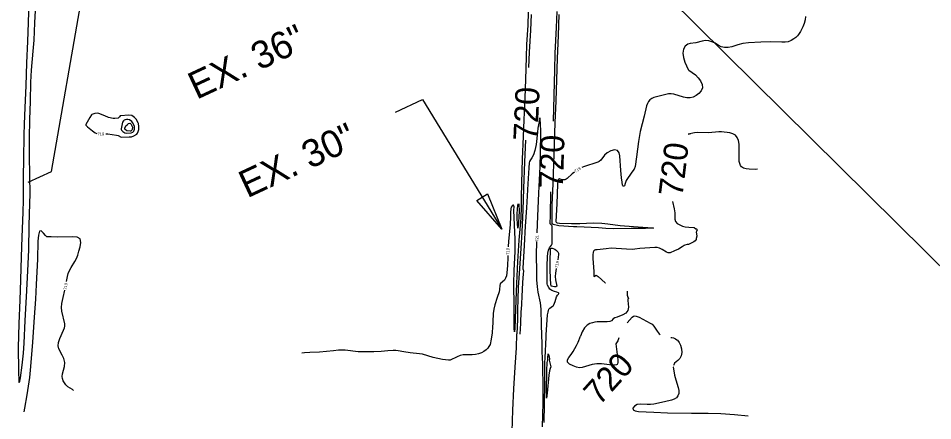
# Model space of a CAD drawing. Extents: x -310467766 to 17062430, y -322263100 to 8322522.
# Drawn here: x 1394958 to 1396211, y 571595 to 572146 of the extents above; entities that cross this region are included whole.
import ezdxf

# ---------------------------------------------------------------- set-up
doc = ezdxf.new("R2010")
doc.units = 0
for name, color, linetype in [('DT_X_Contour_Minor', 7, 'Continuous'), ('Level 19', 7, 'Continuous'), ('Level 40', 7, 'Continuous')]:
    doc.layers.add(name, color=color, linetype=linetype)

msp = doc.modelspace()

# ---------------------------------------------------------------- linework, layer by layer
at = {"layer": 'DT_X_Contour_Minor'}
for points in [[(1394972.9, 572168.3), (1394972, 572140.1), (1394970.9, 572114.2), (1394969.7, 572084.7), (1394968.7, 572053.5), (1394967.4, 572023.7), (1394966.5, 572000.8), (1394965.8, 571986.2), (1394965.3, 571952.4), (1394965.1, 571929.4), (1394965.2, 571897.1), (1394964.7, 571880.6), (1394963.1, 571846.3), (1394962.3, 571819.1), (1394961.5, 571788), (1394960.3, 571759.8), (1394959.2, 571728.2), (1394958.4, 571694.7), (1394958.7, 571664), (1394959.2, 571647.6), (1394959.4, 571647.3), (1394959.8, 571647.5), (1394960.5, 571649.1), (1394961.4, 571653.5), (1394963.8, 571670.9), (1394965.6, 571687.2), (1394966.6, 571700.9), (1394968, 571732), (1394969.8, 571764.6), (1394971.6, 571800.1), (1394972.6, 571828.8), (1394973.4, 571862.3), (1394974.4, 571892.1), (1394974.5, 571905.7), (1394974.2, 571930.3), (1394973.7, 571958.4), (1394973.9, 571981.6), (1394974.3, 572007.5), (1394975.2, 572031.9), (1394975.4, 572058.4), (1394976.3, 572074.9), (1394978.8, 572101.1), (1394980, 572115.8), (1394981.1, 572139.7), (1394982.3, 572165)], [(1395656.8, 572154.4), (1395656, 572136.7), (1395654.5, 572109.9), (1395653.7, 572092.6), (1395652.9, 572062), (1395651.9, 572037.2), (1395650.6, 572007.1), (1395649.6, 571984.1), (1395648.3, 571952.9), (1395647.4, 571920.5), (1395647, 571900), (1395646.9, 571888.1), (1395646.4, 571872.2), (1395645.3, 571857.1), (1395643.9, 571842.1), (1395642.2, 571812.7), (1395640.8, 571782.8), (1395639.4, 571747.7), (1395638.2, 571721.2), (1395637.7, 571716.7), (1395637.5, 571721.2), (1395637.5, 571751.8), (1395637.2, 571782.2), (1395637.6, 571800.8), (1395638.6, 571826.5), (1395638.7, 571843.6), (1395638, 571862.6), (1395637.1, 571883), (1395637.4, 571887.7), (1395637.2, 571889.3), (1395636.7, 571890.1), (1395635.7, 571890), (1395634.6, 571889), (1395633.5, 571887.3), (1395632.9, 571885.1), (1395632.5, 571880.2), (1395632.6, 571874.4), (1395632, 571863), (1395629.8, 571840.7), (1395629.1, 571833.2)], [(1395660.8, 572151.1), (1395659.7, 572129.5), (1395658.1, 572099.3), (1395657.1, 572078.7)], [(1395719.9, 571935.4), (1395716.8, 571932.8), (1395710, 571926.4), (1395708.6, 571925.5), (1395706.9, 571924.9), (1395704.9, 571924.6), (1395702.9, 571924.8), (1395699.4, 571926), (1395698.2, 571925.4), (1395697.4, 571923), (1395697, 571918.8), (1395695.8, 571891.9), (1395694.7, 571867.5), (1395695, 571866.8), (1395695.5, 571866.3), (1395696.3, 571866), (1395699.7, 571865.6), (1395715.8, 571865), (1395727.5, 571864.9), (1395745.6, 571865.7), (1395757.3, 571865.2), (1395765.9, 571864.4), (1395782.6, 571862.1), (1395800.7, 571860.7), (1395826.7, 571859), (1395828.3, 571858.7), (1395827.2, 571858.4), (1395817.1, 571858), (1395797.9, 571858.1), (1395773.7, 571857.8), (1395763.1, 571858.3), (1395752.8, 571858.8), (1395723.1, 571860.2), (1395718.7, 571860.6), (1395698.6, 571861.7), (1395690.9, 571863.5), (1395689.6, 571864.6), (1395689.4, 571865.2), (1395689.4, 571873.7), (1395689.7, 571890.7), (1395690.7, 571919.1), (1395691.7, 571946.5), (1395692.5, 571973.7), (1395693.6, 572003.2), (1395694.8, 572032.4), (1395695.7, 572062.1), (1395696.6, 572091), (1395698, 572122.4), (1395699.3, 572151.2)], [(1395691.4, 572004.9), (1395692.4, 572040.4), (1395693, 572075.5), (1395693.8, 572098.1), (1395695.5, 572133.5), (1395696.3, 572155.1)], [(1396036.6, 572148.3), (1396036, 572143.8), (1396034.6, 572138.9), (1396032.8, 572134.3), (1396029.5, 572127.8), (1396026.9, 572123.6), (1396025.4, 572121.8), (1396023.4, 572119.8), (1396020.4, 572117.6), (1396016.6, 572115.5), (1396012.5, 572113.9), (1396008.4, 572113.2), (1396004.2, 572113), (1395988.5, 572113.7), (1395975.3, 572113.4), (1395958.5, 572112.4), (1395950.6, 572111.4), (1395943.7, 572109.7), (1395935.4, 572107), (1395930.5, 572105.9), (1395925.6, 572105.7), (1395921, 572107), (1395916.7, 572109.3), (1395912.5, 572111.7), (1395908.3, 572113.8), (1395904.1, 572115.1), (1395899.7, 572115.4), (1395895.1, 572114.6), (1395886.2, 572112.1), (1395878.6, 572111.3), (1395875.1, 572110.3), (1395871.8, 572107.7), (1395869.3, 572103.7), (1395868.3, 572098.3), (1395869.2, 572092), (1395871.3, 572085.8), (1395875.7, 572075.9), (1395876.8, 572074.8), (1395885.6, 572068.4), (1395889.5, 572064.6), (1395892.8, 572060.1), (1395894.9, 572055.4), (1395895.2, 572050.7), (1395893.5, 572046.5), (1395890.3, 572042.9), (1395886.5, 572040), (1395882.6, 572037.9), (1395878.5, 572036.9), (1395874.1, 572036.8), (1395869.2, 572037.8), (1395855.9, 572042), (1395852.5, 572042.5), (1395849, 572042.4), (1395845, 572041.7), (1395832.5, 572038.4), (1395828.9, 572037.3), (1395825.8, 572036), (1395823.3, 572034.3), (1395821.3, 572032.1), (1395819.9, 572029.3), (1395818.8, 572026), (1395815.6, 572011.9), (1395810, 571991.1), (1395807.7, 571977.3), (1395804.8, 571956), (1395803.2, 571943), (1395801.6, 571939.4), (1395798.8, 571935), (1395790.8, 571923.8), (1395789.7, 571921.1), (1395789, 571918.2), (1395788.9, 571917.3), (1395788.4, 571916.6), (1395787.7, 571916.2), (1395786.9, 571916.2), (1395786.3, 571916.6), (1395786, 571917.3), (1395785.5, 571921.4), (1395784.5, 571927.5), (1395783.6, 571937.6), (1395782.3, 571957.4), (1395781.2, 571961.7), (1395778.8, 571964.7), (1395774.8, 571965.6), (1395769.8, 571964.5), (1395765, 571961.9), (1395761.3, 571958.4), (1395756, 571951.6), (1395753.9, 571949.7), (1395752, 571948.7), (1395732.6, 571942.5), (1395730.3, 571941.5)], [(1395078.1, 571987.5), (1395080.9, 571987.6), (1395093, 571985.8), (1395095.3, 571985.2), (1395099.4, 571983), (1395110.3, 571983.4), (1395113.3, 571983.7), (1395116.5, 571984.9), (1395120.5, 571987.1), (1395121.7, 571988.7), (1395122.6, 571990.8), (1395123.4, 571993.6), (1395123.4, 571997.9), (1395122.8, 572001.7), (1395122.4, 572002.8), (1395119.6, 572007.7), (1395117.6, 572009.9), (1395115.9, 572011.4), (1395113.7, 572012.6), (1395109.6, 572013.1), (1395098.4, 572012.5), (1395097.7, 572012.2), (1395096.8, 572011), (1395095.7, 572009.4), (1395095.2, 572009.1), (1395090.8, 572008.7), (1395088.1, 572008.8), (1395082, 572010.2), (1395077.1, 572012.2), (1395068.8, 572015.7), (1395066.7, 572015.9), (1395063.2, 572015.6), (1395059.3, 572014.1), (1395058.7, 572013.7), (1395056.3, 572009.9), (1395052.5, 572003.6), (1395050.8, 572000.5), (1395051, 571999.8), (1395053.2, 571997.5), (1395059.9, 571991.8), (1395063.6, 571989.3), (1395066.1, 571988.2)], [(1395106.7, 572007.2), (1395104.7, 572006.9), (1395103.4, 572006.4), (1395102.4, 572005.5), (1395101.3, 572003.5), (1395099.1, 571994.7), (1395099.1, 571993.8), (1395099.6, 571992.8), (1395101.7, 571990.7), (1395104.3, 571988.9), (1395106.7, 571988.7), (1395113.1, 571989), (1395115.3, 571990.1), (1395116.5, 571991.2), (1395117.2, 571992.6), (1395117.5, 571994.2), (1395117.5, 571997.8), (1395116.7, 572000.1), (1395115, 572003.2), (1395113.7, 572004.5), (1395110.7, 572006.8), (1395108.3, 572007.2), (1395106.7, 572007.2)], [(1395112.4, 572001.5), (1395114.6, 571996.7), (1395114.5, 571993.5), (1395114, 571992.6), (1395112.5, 571991.5), (1395111.4, 571991.2), (1395106.9, 571991.9), (1395104.8, 571993.5), (1395104.2, 571994.3), (1395104.5, 571995.5), (1395105.8, 571998.7), (1395107.5, 572000.2), (1395109.5, 572001.7), (1395111.2, 572002.3), (1395112, 572002), (1395112.4, 572001.5)], [(1395668.9, 571852.1), (1395669.8, 571875.2), (1395671.1, 571906.4), (1395673.1, 571943.1), (1395673.6, 571961.3), (1395673.8, 571989.9), (1395673.4, 572002.9), (1395672.8, 572009.4), (1395672.4, 572008.5), (1395669.9, 571995.4), (1395669.2, 571990.2), (1395667.4, 571973.2), (1395665.9, 571964.9), (1395663.8, 571958.9), (1395661.6, 571954.9), (1395659.8, 571952.1), (1395658.6, 571949.9), (1395658.1, 571947.9), (1395657.6, 571941.3), (1395656.2, 571919.1), (1395654.4, 571886.4), (1395652.6, 571861.2), (1395651.2, 571834.9), (1395649.3, 571803.9), (1395649.5, 571802.4), (1395649.8, 571801.8), (1395650.1, 571799.6), (1395649.9, 571795.9), (1395648.9, 571784), (1395647.8, 571764.8), (1395647.6, 571755), (1395646.9, 571747.3), (1395646.6, 571744.8), (1395646.3, 571728), (1395645.4, 571713.6)], [(1395970.5, 571939.2), (1395967.7, 571939.1), (1395959.4, 571939.5), (1395955.2, 571940), (1395951.6, 571940.9), (1395949, 571942.5), (1395947.3, 571944.5), (1395946.3, 571947), (1395945.8, 571949.7), (1395945.8, 571957.1), (1395945.8, 571968), (1395945.4, 571973.6), (1395944.5, 571978.7), (1395942.9, 571982.9), (1395940.4, 571986), (1395936.9, 571987.9), (1395932.8, 571988.9), (1395921.4, 571990.3), (1395917.6, 571990.3), (1395903.7, 571989.2), (1395889.2, 571989.6), (1395884.3, 571989.1), (1395875.6, 571987.3), (1395879.4, 571988.1)], [(1395652.8, 571979.2), (1395651.7, 571949.2), (1395650.3, 571912.8), (1395649.3, 571883.1), (1395648, 571853.7), (1395646.4, 571830.8), (1395644.6, 571803.4), (1395643.1, 571777.4), (1395642.3, 571761.2), (1395642.2, 571746.8), (1395642.1, 571733.7), (1395641.3, 571713.8)], [(1395681.4, 571712.3), (1395682, 571726.2), (1395683, 571739.8), (1395683.8, 571743.4), (1395684.6, 571746), (1395685.1, 571747.5), (1395686.3, 571748.8), (1395690, 571751.7), (1395691.4, 571752.7), (1395691.9, 571753.6), (1395693.5, 571758.3), (1395695.4, 571764.5), (1395696.7, 571767), (1395698, 571768.1), (1395698.5, 571768.9), (1395698.6, 571769.5), (1395698.1, 571770), (1395695.7, 571770.7), (1395692.5, 571771.8), (1395688.9, 571773.4), (1395686.5, 571775.2), (1395684.8, 571777.4), (1395683.1, 571780.3), (1395682.8, 571782.5), (1395682.5, 571790.8), (1395682.8, 571806.9), (1395683.2, 571819.4), (1395683.6, 571824.4), (1395684.4, 571828.6), (1395685.8, 571831.5), (1395688.5, 571835.2), (1395689.3, 571837.3), (1395689.6, 571840), (1395689.6, 571853.2), (1395689.5, 571861.2), (1395689.1, 571862), (1395687.5, 571863.4), (1395686.9, 571864.3), (1395686.7, 571865.6), (1395687.2, 571875.5), (1395687.6, 571908.3)], [(1395642.3, 571858.5), (1395641.5, 571871.5), (1395641.6, 571878), (1395642, 571884.7), (1395642.7, 571890.1), (1395643.4, 571892.5), (1395643.8, 571891.1), (1395644.2, 571882), (1395644, 571874), (1395643.4, 571866.7), (1395642.3, 571858.5)], [(1395854.2, 571895.2), (1395856.5, 571884.8), (1395857.3, 571879.5), (1395857.4, 571871.1), (1395858.3, 571867.8), (1395860.8, 571865.1), (1395864.4, 571862.9), (1395868.2, 571861.4), (1395871.7, 571860.5), (1395876.7, 571859.9), (1395883.9, 571859.3), (1395886.1, 571857.8), (1395887.1, 571857.5), (1395887.7, 571857), (1395887.9, 571856.1), (1395887.2, 571854.1), (1395886.7, 571853), (1395887, 571850.7), (1395887.4, 571847.4), (1395886.9, 571844.3), (1395886.6, 571842.9), (1395885.5, 571841.3), (1395883.4, 571839.7), (1395877.3, 571836.5), (1395876.2, 571836.2), (1395874.4, 571836.1), (1395871.2, 571835.4), (1395870.1, 571834.7), (1395867.4, 571832.9), (1395862.4, 571829.9), (1395857.1, 571827.4), (1395850.9, 571825), (1395849.8, 571824.7), (1395848.4, 571824.9), (1395846.3, 571825.8), (1395840.2, 571829.5), (1395836.7, 571831.2), (1395833.4, 571832.1), (1395830.2, 571832.2), (1395809.4, 571830.5), (1395802.8, 571830), (1395799.4, 571829.5), (1395791.4, 571829.9), (1395770.5, 571831), (1395763.4, 571830.3), (1395751, 571829), (1395749, 571828.8), (1395747.7, 571828.4), (1395746.5, 571827.4), (1395745.7, 571825.5), (1395745.2, 571822.1), (1395745.3, 571817.1), (1395746.5, 571799), (1395746.4, 571794.3), (1395746.6, 571792.8), (1395747.1, 571792.6), (1395748.9, 571793.9), (1395749.7, 571794.1), (1395751.1, 571793.5), (1395752.7, 571792.2), (1395762.3, 571783.7), (1395762.5, 571783.5)], [(1395024.4, 571785.4), (1395025.7, 571792.4), (1395026.8, 571796.4), (1395028.3, 571800.4), (1395030.6, 571804.5), (1395035.8, 571813), (1395037.9, 571817.2), (1395039.7, 571821.6), (1395041.5, 571826.9), (1395043.3, 571833), (1395044.2, 571839.1), (1395043, 571843.9), (1395038.8, 571846.2), (1395032.6, 571846.8), (1395011.8, 571846.3), (1395003.5, 571846.6), (1395000.2, 571846.9), (1394999, 571846.7), (1394997.6, 571846.9), (1394995.6, 571848.5), (1394992.9, 571851.8), (1394989.8, 571854.7), (1394987.3, 571854.4), (1394985.9, 571848.9), (1394985.3, 571840.6), (1394984.7, 571816.2), (1394983, 571781.6), (1394981.9, 571761.2), (1394980.2, 571736.7), (1394978, 571702.4), (1394975.1, 571669), (1394973.5, 571654.3), (1394970.1, 571630.4), (1394967.1, 571611.9), (1394966.1, 571607.2)], [(1395675.5, 571712.5), (1395675.1, 571725.7), (1395674.3, 571747.5), (1395673.3, 571756.5), (1395670.5, 571770.8), (1395669.5, 571778.3), (1395668.7, 571787.7), (1395668.3, 571799.3), (1395668.1, 571821.4), (1395668.5, 571840.1)], [(1395695.2, 571803.5), (1395694.1, 571797.1), (1395693.7, 571792.3), (1395694, 571788), (1395695.8, 571779), (1395694.6, 571778.2), (1395692.5, 571778.2), (1395688.3, 571779.3), (1395687.9, 571779.9), (1395687.7, 571781), (1395686.7, 571800.6), (1395686.9, 571811.9), (1395687.4, 571830.7), (1395688.4, 571831.2), (1395689.4, 571831.3), (1395691, 571830.9), (1395693.1, 571829.7), (1395695.3, 571828), (1395697.2, 571826.2), (1395698.1, 571824.5), (1395698.3, 571822.5), (1395697.1, 571815.4)], [(1395628.7, 571821.2), (1395628.6, 571818.4), (1395628.5, 571807.3), (1395627.6, 571797.2), (1395626.9, 571793.1), (1395625.7, 571789.9), (1395624.1, 571787.4), (1395618.4, 571782.3), (1395617.6, 571780.2), (1395617.3, 571774.7), (1395616.7, 571771.5), (1395614.3, 571763.7), (1395611, 571753.4), (1395609.6, 571747.6), (1395608.7, 571741.6), (1395608.1, 571730.4), (1395607.8, 571721.5), (1395607.4, 571716.9), (1395607.1, 571715.1)], [(1395034, 571636.5), (1395032.4, 571637.7), (1395026.1, 571641.5), (1395023.5, 571644), (1395021.5, 571646.8), (1395020, 571649.7), (1395018.9, 571652.5), (1395018.5, 571655.6), (1395018.9, 571659.3), (1395021.5, 571669.2), (1395021.9, 571674.6), (1395020.7, 571679.9), (1395018.5, 571684.8), (1395014.1, 571693.2), (1395013.1, 571697.3), (1395013.5, 571702), (1395015.2, 571707.7), (1395020.1, 571718.7), (1395021.6, 571722), (1395022.1, 571724.5), (1395021.9, 571727.4), (1395018, 571744.7), (1395017.7, 571750), (1395018, 571755.2), (1395019.7, 571763.5), (1395022, 571773.7)], [(1395792.3, 571772.5), (1395792.4, 571766.8), (1395792.9, 571763.9), (1395793.7, 571762.8), (1395794.5, 571762.5), (1395793.8, 571762.4), (1395793, 571761.5), (1395792.9, 571759.3), (1395794, 571750.4), (1395793.3, 571745.7), (1395790.6, 571742.2), (1395786.5, 571739.8), (1395778.3, 571736.8), (1395775.2, 571735.7), (1395773.1, 571734.6), (1395770.7, 571731.9), (1395768.5, 571730.9), (1395764.7, 571730.5), (1395751.2, 571730.3), (1395747.8, 571729.9), (1395744.6, 571729.1), (1395741.1, 571727.8), (1395737.5, 571725.7), (1395734, 571722), (1395730.8, 571716.7), (1395728.2, 571710.8), (1395728.1, 571710.5)], [(1395792, 571728.9), (1395798.9, 571736.5), (1395801.1, 571738.1), (1395802.9, 571738.5), (1395804.6, 571738.1), (1395808.5, 571736.5), (1395823.9, 571728.6), (1395826.4, 571726.9), (1395828.6, 571724.5), (1395833.1, 571717.4), (1395835.9, 571714.1), (1395837.5, 571713)], [(1395607.2, 571715.1), (1395605.9, 571706.6), (1395604.5, 571699.2), (1395602.9, 571696.5), (1395601.3, 571694.2), (1395599, 571691.9), (1395596.1, 571689.8), (1395592.6, 571688), (1395588.6, 571686.6), (1395584.3, 571685.8), (1395579.9, 571685.3), (1395567.7, 571685), (1395563.6, 571684.2), (1395559.4, 571682.6), (1395549.7, 571677.8), (1395547.5, 571677.6), (1395539.1, 571678.7), (1395532.9, 571679.9), (1395526.6, 571681.3), (1395512.1, 571685.9), (1395508, 571686.6), (1395495.2, 571687.7), (1395486.5, 571689.1), (1395478.8, 571690.6), (1395475.3, 571691.1), (1395471.9, 571691.2), (1395464.6, 571690.6), (1395455.3, 571689.8), (1395445.3, 571689.3), (1395424, 571689.2), (1395405.9, 571691.4), (1395397, 571691.3), (1395389.9, 571690.8), (1395370.7, 571688.7), (1395357.8, 571688.5), (1395350.2, 571688), (1395346.5, 571687.3)], [(1395640.5, 571694.6), (1395641.3, 571713.8)], [(1395676.2, 571586.4), (1395677.1, 571619.2), (1395677.1, 571637.9), (1395676.5, 571672.7), (1395676, 571689.3), (1395676, 571700.1), (1395675.5, 571712.5)], [(1395678.4, 571592.6), (1395679.2, 571617.8), (1395679.4, 571646.9), (1395679.6, 571674.5), (1395680.1, 571681.1), (1395681.3, 571709.5), (1395681.4, 571712.3)], [(1395780.8, 571708.5), (1395779.2, 571704.2), (1395776.6, 571700), (1395778.1, 571689.4), (1395779.3, 571678.2), (1395779.4, 571674.7), (1395779.1, 571672.7), (1395778.4, 571671.8), (1395777.5, 571671.3), (1395775, 571671.2), (1395771.5, 571671.2), (1395757.1, 571672.9), (1395750.6, 571672.8), (1395744.4, 571671.7), (1395730.4, 571667.6), (1395727, 571667.5), (1395723, 571668.3), (1395718.1, 571670), (1395713.4, 571672.4), (1395710.4, 571675.2), (1395710.3, 571678.3), (1395712.3, 571681.6), (1395715.3, 571685.5), (1395718.3, 571689.9), (1395722.9, 571697.8), (1395725.1, 571702.5), (1395728.1, 571710.5)], [(1395851.9, 571709), (1395853.2, 571708.8), (1395855.8, 571708.2), (1395858.5, 571707), (1395860.4, 571705.5)], [(1395860.4, 571705.5), (1395861.1, 571705), (1395863.4, 571702.1), (1395865.3, 571698.3), (1395866.6, 571693.5), (1395867, 571688.4), (1395866.3, 571683.7), (1395864.4, 571680.1), (1395861.8, 571677.5), (1395857.2, 571673.7), (1395855.9, 571671.5), (1395855.7, 571670.3)], [(1395634.8, 571580), (1395635.8, 571609.4), (1395637.1, 571638.6), (1395638.9, 571668.2), (1395640.5, 571694.6)], [(1395683.4, 571678.2), (1395683.5, 571681.7), (1395683.8, 571685.6), (1395684.1, 571686.4), (1395684.6, 571685.8), (1395685.6, 571682.2), (1395685.7, 571679.4), (1395685.6, 571677.6), (1395687.5, 571668.6), (1395686.8, 571666.5), (1395685.7, 571663), (1395685, 571657.5), (1395682.5, 571632.6), (1395681.6, 571626), (1395681.7, 571635), (1395682, 571663.8), (1395682.8, 571674.5), (1395683.4, 571678.2)], [(1395855.5, 571668.4), (1395855.4, 571668.2), (1395855.9, 571663.2), (1395857.1, 571657.2), (1395858.8, 571651.1), (1395862.1, 571640.5), (1395863, 571636.1), (1395862.8, 571632.2), (1395861.7, 571628.9), (1395859.6, 571626.2), (1395856.6, 571624.3), (1395852.9, 571622.9), (1395843.5, 571620.7), (1395828.5, 571617.7), (1395824, 571617.1), (1395819.4, 571617), (1395810.1, 571617.6), (1395805.9, 571616.9), (1395802.3, 571614.9), (1395800.1, 571612.2), (1395800.2, 571609.8), (1395803.1, 571608.3), (1395807.6, 571607.6), (1395828.9, 571606.6), (1395847.4, 571605.8), (1395880.3, 571605.4), (1395903.1, 571605.1), (1395920.6, 571604.7), (1395939.4, 571603.2), (1395957.8, 571601.7)]]:
    msp.add_lwpolyline(points, dxfattribs=at)
at = {"layer": 'Level 40'}
for p, q in [((1395684.8, 572337.1), (1396318.1, 571710.2)), ((1395003.7, 571936.2), (1395061.7, 572268.9)), ((1395475, 572017.2), (1395512, 572034.5)), ((1395512, 572034.5), (1395620.7, 571857)), ((1394972.1, 571921.5), (1395003.7, 571936.2)), ((1395586.4, 571896.5), (1395601.1, 571905.5)), ((1395601.1, 571905.5), (1395620.7, 571857)), ((1395620.7, 571857), (1395586.4, 571896.5))]:
    msp.add_line(p, q, dxfattribs=at)

# ---------------------------------------------------------------- texts
at = {"layer": 'Level 19'}
for s, height, rotation, p in [('720', 33, 87.4735, (1395669.2, 571977.6)), ('719', 4, 0.2807, (1395066.9, 571985.5)), ('720', 33, 88.2355, (1395704.2, 571912.2)), ('720', 33, 83.1304, (1395867.8, 571900.6)), ('719', 4, 32.3435, (1395721.5, 571934.3)), ('721', 4, 87.9146, (1395670.5, 571839.9)), ('719', 4, 89.2267, (1395630.7, 571822)), ('719', 4, 80.6553, (1395697.3, 571803.9)), ('719', 4, 79.2343, (1395024.3, 571774)), ('720', 33, 48.0883, (1395754.2, 571614.5))]:
    msp.add_text(s, height=height, rotation=rotation, dxfattribs=at).set_placement(p)
at = {"layer": 'Level 40'}
for s, p in [('EX. 36"', (1395202.5, 572034.1)), ('EX. 30"', (1395271.9, 571899.2))]:
    msp.add_text(s, height=37.5, rotation=25, dxfattribs=at).set_placement(p)

doc.saveas('drawing.dxf')
